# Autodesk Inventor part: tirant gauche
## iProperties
Shininess: 64.0
Length Units: 11269
Angle Units: 11279
Time Units: 11290
Mass Units: 11283
Length Display Precision: 3
Angle Display Precision: 2
Compacted: True
Part Number: tirant gauche
Document SubType Name: Modeling
Created: 2004-12
Material: Par défaut
Designer: LEGERET Philippe
Density: 0.0
Volumn: 0.0
Area: 0.0
PropertySet Name: Model Information
Control State: 0
Master: False
Checked Out: False
Author: LEGERET Philippe
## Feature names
1. Révolution1 [Revolution]
2. Extrusion1
3. Chanfrein1 [Chamfer]
